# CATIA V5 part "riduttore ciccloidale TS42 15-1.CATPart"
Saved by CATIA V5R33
Part number: riduttore ciccloidale TS42 15-1
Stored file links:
  C:\Users\Ryzen5700u\Desktop\robot_cicloidale_singolo\Assieme_robot_cicloidale_singolo\riduttore ciccloidale TS42 15-1.CATPart

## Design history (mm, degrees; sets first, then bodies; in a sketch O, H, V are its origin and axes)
Body1 "Solido1" (main body)
  Solid1: solid without history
